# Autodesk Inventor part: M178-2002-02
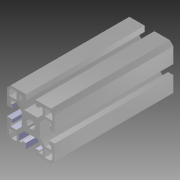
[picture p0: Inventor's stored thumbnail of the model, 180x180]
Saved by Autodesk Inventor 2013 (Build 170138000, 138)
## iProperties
Created: 2004-10
Material: Aluminium - 6061
Document SubType Name: Modeling
Designer: Autodesk, Inc.
Manufacturer: Standard
Standards Organization: Custom
Description: PC RACK, UPRIGHT, RIGHT
Stock Number: 10-540
Catalog Web Link: http://www.parker.com/ead/cm1.asp?cmid=809
Vendor: PARKER IPS
Part Number: M178-2002-02
Mass: 179.948 g
Surface Area: 483.565 cm^2
Volume: 66.4013 cm^3
Density: 2.71 g/cm^3
CAGE: 1LJX3
Dept. ID: Product Design
Description #2: ---
Finish #1: ---
Finish #2: ---
Material ID: ---
Project Number: ---
Stock Number: 10-040
Length: 184.150 mm
Author: Autodesk, Inc.
Revision Number: A
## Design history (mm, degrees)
derived "40 Series Profiles.ipt"
feature "IPS40SeriesCutout1"
feature "IPS40SeriesCutout2"
body "Solid1"
tag "TaggingFeature2"
sketch "Sketch1"
  geometry: L1 (20, 64.3)-(7, -119.85) reference; L2 (7, 64.3)-(7, -119.85) reference; L3 (-1, -119.85)-(-1, 64.3) reference; L4 (7, 44.3)-(-1, 44.3); C1 r 10 at (3, 44.3)
  constraints: 2 end point, 2 point on line, 1 centre point, 1 midpoint, 1 perpendicular
  dimensions: "d0" = 20 distance between parallel lines of L4 L1; "d1" = 20 diameter of C1
sketch "Sketch2"
  geometry: L1 (-56.35, -43.5)-(-56.35, -43.5) reference; L2 (127.8, -43.5)-(-56.35, -43.5) reference; L3 (-56.35, -35.5)-(127.8, -35.5) reference; L4 (-36.35, -43.5)-(-36.35, -35.5); C1 r 10 at (-36.35, -39.5)
  constraints: 2 end point, 2 point on line, 1 centre point, 1 midpoint, 1 perpendicular
  dimensions: "d2" = 20 distance between parallel lines of L4 L1; "d3" = 20 diameter of C1
feature "Solid1::40 Series Profiles.ipt" dims "ScaleForDerivedMember" = 10
other parameters: "Length" = 184.15
